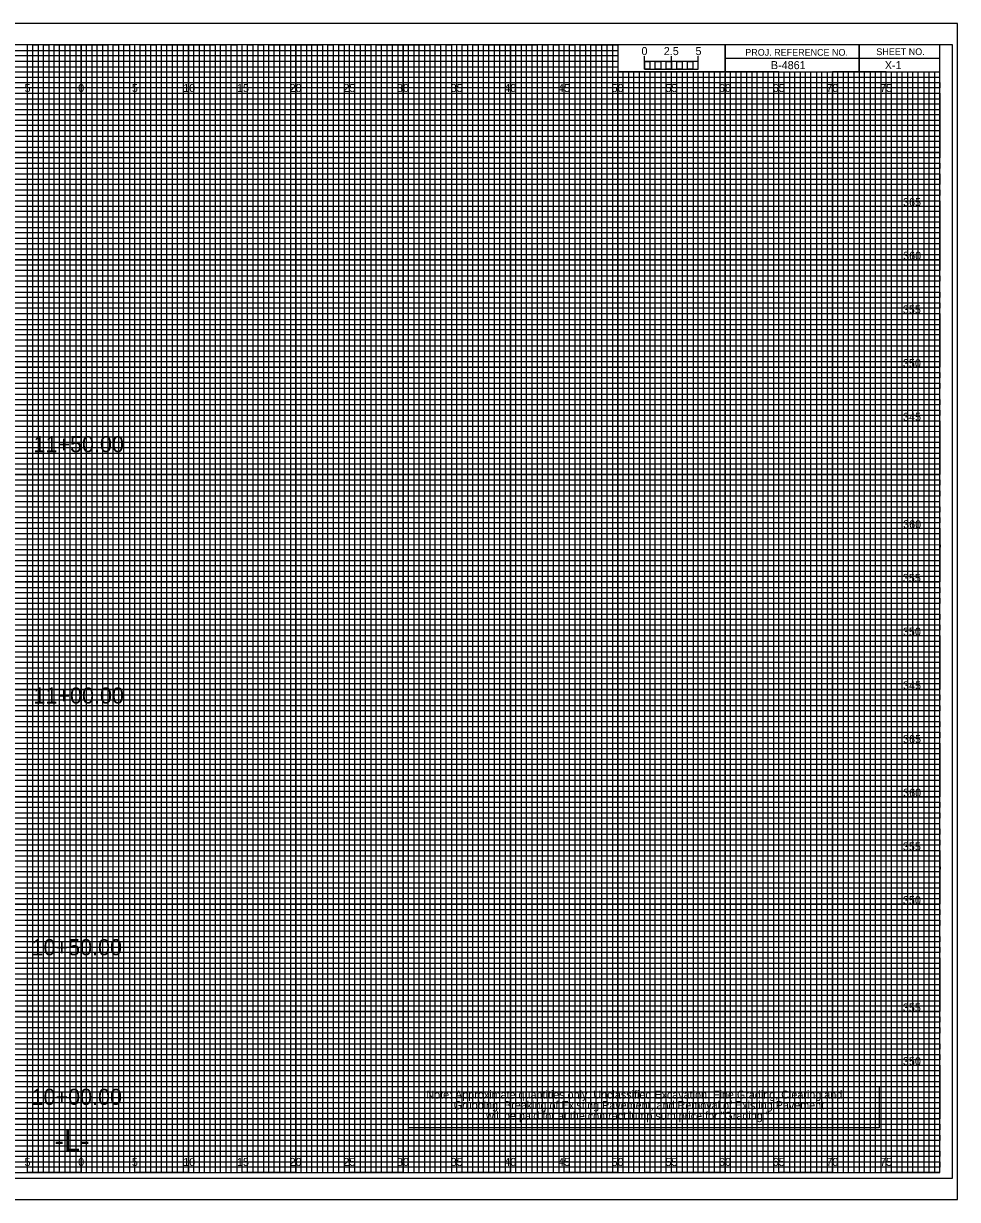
# Model space of a CAD drawing. Extents: x -7 to 266, y -5 to 437.
# Drawn here: x 74.6 to 161.7, y -2.5 to 107 of the extents above; entities that cross this region are included whole.
import ezdxf

# ---------------------------------------------------------------- set-up
doc = ezdxf.new("R2010")
doc.units = 0
for name, color, linetype in [('Exist XS Center Line Elevation Label', 7, 'Continuous'), ('Exist XS Ground Line', 7, 'Continuous'), ('Prop XS Dump Level', 7, 'Continuous'), ('Prop XS EOT Tick Mark', 7, 'Continuous'), ('Prop XS Finish Grade', 7, 'Continuous'), ('Prop XS Finish Grade Concrete', 7, 'Continuous'), ('Prop XS Finish Grade CurbGutter', 7, 'Continuous'), ('Prop XS Finish Grade Earthwork', 7, 'Continuous'), ('Prop XS Finish Grade Pavement', 7, 'Continuous'), ('Prop XS Geopak Shape', 7, 'Continuous'), ('Prop XS Hydro Elevations', 7, 'Continuous'), ('Prop XS Pvmt Edge Slope', 7, 'Continuous'), ('Prop XS SE Text', 7, 'Continuous'), ('Prop XS Side Slope Text', 7, 'Continuous'), ('Prop XS SS Elevation Text', 7, 'Continuous'), ('Prop XS Subgrade CurbGutter', 7, 'Continuous'), ('Prop XS Subgrade Earthwork', 7, 'Continuous'), ('Prop XSC Text', 7, 'Continuous'), ('Typical Guardrail CELL', 7, 'Continuous')]:
    doc.layers.add(name, color=color, linetype=linetype)

msp = doc.modelspace()

# ---------------------------------------------------------------- linework, layer by layer
at = {"layer": 'Exist XS Center Line Elevation Label'}
for points in [[(72.5, 0), (77.5, 0), (77.5, 105), (82.5, 105), (82.5, 0), (87.5, 0), (87.5, 105), (92.5, 105), (92.5, 0), (97.5, 0), (97.5, 105), (102.5, 105), (102.5, 0), (107.5, 0), (107.5, 105), (112.5, 105), (112.5, 0), (117.5, 0), (117.5, 105), (122.5, 105), (122.5, 0), (127.5, 0), (127.5, 105), (129.97, 105), (130, 105), (130, 102.5), (132.5, 102.5), (132.5, 0), (137.5, 0), (137.5, 102.5), (142.5, 102.5), (142.5, 0), (147.5, 0), (147.5, 102.5), (152.5, 102.5), (152.5, 0), (157.5, 0), (157.5, 102.5)], [(0, 102.5), (137.5, 102.5)], [(0, 92.5), (160, 92.5), (160, 97.5), (0, 97.5)], [(0, 82.5), (160, 82.5), (160, 87.5), (0, 87.5)], [(0, 72.5), (160, 72.5), (160, 77.5), (0, 77.5)], [(0, 62.5), (160, 62.5), (160, 67.5), (0, 67.5)], [(0, 52.5), (160, 52.5), (160, 57.5), (0, 57.5)], [(0, 42.5), (160, 42.5), (160, 47.5), (0, 47.5)], [(0, 32.5), (160, 32.5), (160, 37.5), (0, 37.5)], [(0, 22.5), (160, 22.5), (160, 27.5), (0, 27.5)], [(0, 12.5), (160, 12.5), (160, 17.5), (0, 17.5)], [(0, 2.5), (160, 2.5), (160, 7.5), (0, 7.5)]]:
    msp.add_lwpolyline(points, dxfattribs=at)
at = {"layer": 'Exist XS Ground Line'}
for p, q in [((75, 105), (70, 105)), ((75, 0), (75, 105)), ((85, 105), (80, 105)), ((80, 105), (80, 0)), ((85, 0), (85, 105)), ((95, 105), (90, 105)), ((90, 105), (90, 0)), ((95, 0), (95, 105)), ((105, 105), (100, 105)), ((100, 105), (100, 0)), ((105, 0), (105, 105)), ((115, 105), (110, 105)), ((110, 105), (110, 0)), ((115, 0), (115, 105)), ((125, 105), (120, 105)), ((120, 105), (120, 0)), ((125, 0), (125, 105)), ((130, 105), (130, 0)), ((135, 0), (135, 102.5)), ((145, 102.5), (140, 102.5)), ((140, 102.5), (140, 0)), ((145, 0), (145, 102.5)), ((155, 102.5), (150, 102.5)), ((150, 102.5), (150, 0)), ((155, 0), (155, 102.5)), ((80, 0), (75, 0)), ((90, 0), (85, 0)), ((100, 0), (95, 0)), ((110, 0), (105, 0)), ((120, 0), (115, 0)), ((130, 0), (125, 0)), ((140, 0), (135, 0)), ((150, 0), (145, 0)), ((160, 0), (155, 0)), ((160, 0), (160, 0))]:
    msp.add_line(p, q, dxfattribs=at)
for points in [[(0, 100), (160, 100), (160, 95), (0, 95)], [(0, 90), (160, 90), (160, 85), (0, 85)], [(0, 80), (160, 80), (160, 75), (0, 75)], [(0, 70), (160, 70), (160, 65), (0, 65)], [(0, 60), (160, 60), (160, 55), (0, 55)], [(0, 50), (160, 50), (160, 45), (0, 45)], [(0, 40), (160, 40), (160, 35), (0, 35)], [(0, 30), (160, 30), (160, 25), (0, 25)], [(0, 20), (160, 20), (160, 15), (0, 15)], [(0, 10), (160, 10), (160, 5), (0, 5)]]:
    msp.add_lwpolyline(points, dxfattribs=at)
at = {"layer": 'Prop XS Finish Grade'}
for p, q in [((75, 0), (75, 105)), ((80, 0), (80, 105)), ((85, 0), (85, 105)), ((90, 0), (90, 105)), ((95, 0), (95, 105)), ((100, 0), (100, 105)), ((105, 0), (105, 105)), ((110, 0), (110, 105)), ((115, 0), (115, 105)), ((120, 0), (120, 105)), ((125, 0), (125, 105)), ((130, 0), (130, 102.34)), ((135, 0), (135, 102.34)), ((140, 0), (140, 102.34)), ((145, 0), (145, 102.34)), ((150, 0), (150, 102.34)), ((155, 0), (155, 102.34)), ((0, 100), (160, 100)), ((0, 95), (160, 95)), ((0, 90), (160, 90)), ((0, 85), (160, 85)), ((0, 80), (160, 80)), ((0, 75), (160, 75)), ((0, 70), (160, 70)), ((0, 65), (160, 65)), ((0, 60), (160, 60)), ((0, 55), (160, 55)), ((0, 50), (160, 50)), ((0, 45), (160, 45)), ((0, 40), (160, 40)), ((0, 35), (160, 35)), ((0, 30), (160, 30)), ((0, 25), (160, 25)), ((0, 20), (160, 20)), ((0, 15), (160, 15)), ((0, 10), (160, 10)), ((0, 5), (160, 5))]:
    msp.add_line(p, q, dxfattribs=at)
at = {"layer": 'Prop XS Finish Grade Earthwork'}
msp.add_lwpolyline([(-6.7, -2.5), (161.65, -2.5), (161.65, 107), (-6.7, 107)], close=True, dxfattribs=at)
at = {"layer": 'Prop XS Hydro Elevations'}
for p, q in [((152.5, 105), (152.5, 102.5)), ((152.5, 102.5), (152.5, 105)), ((160, 103.75), (140, 103.75)), ((140, 103.75), (140, 102.5)), ((140, 102.5), (160, 102.5))]:
    msp.add_line(p, q, dxfattribs=at)
for points in [[(160, 105), (0, 105), (0, 0), (160, 0)], [(140, 105), (130, 105), (130, 102.52), (140, 102.52)], [(160, 105), (140, 105), (140, 102.5), (160, 102.5)]]:
    msp.add_lwpolyline(points, close=True, dxfattribs=at)
at = {"layer": 'Prop XS Pvmt Edge Slope'}
msp.add_lwpolyline([(-5.4, -0.5), (161.2, -0.5), (161.2, 105), (-5.4, 105)], close=True, dxfattribs=at)
at = {"layer": 'Prop XS SE Text'}
for p, q in [((0, 104.5), (130, 104.5)), ((130, 104.5), (130, 103.99)), ((130, 103.99), (0, 103.99)), ((0, 103.5), (130, 103.5)), ((130, 102.95), (0, 102.95)), ((130, 103.5), (130, 102.95)), ((0, 102), (160, 102))]:
    msp.add_line(p, q, dxfattribs=at)
for points in [[(0, 101.5), (135, 101.5), (160, 101.5), (160, 101), (0, 101)], [(0, 100.5), (160, 100.5), (160, 99.5), (0, 99.5)], [(0, 99), (160, 99), (160, 98.5), (0, 98.49)], [(0, 98), (160, 98), (160, 97), (0, 97)], [(0, 96.5), (160, 96.5), (160, 96), (0, 96)], [(0, 95.5), (160, 95.5), (160, 94.5), (0, 94.5)], [(0, 94), (160, 94), (160, 93.5), (0, 93.5)], [(0, 93), (160, 93), (160, 92), (0, 92)], [(0, 91.5), (160, 91.5), (160, 91), (0, 91)], [(0, 90.5), (160, 90.5), (160, 89.5), (0, 89.5)], [(0, 89), (160, 89), (160, 88.5), (0, 88.5)], [(0, 88), (160, 88), (160, 86.98), (160, 86.5), (160, 86), (0, 86)], [(0, 87), (160, 87), (160, 86.5), (0, 86.5)], [(0, 85.5), (160, 85.5), (160, 84.5), (0, 84.52)], [(0, 84.52), (160, 84.5), (160, 84), (0, 84)], [(0, 83.5), (160, 83.5), (160, 83), (0, 83)], [(0, 82), (160, 82), (160, 81.5), (0, 81.5)], [(0, 81), (160, 81), (160, 80.5), (0, 80.5)], [(-0.04, 79.45), (160, 79.45), (160, 78.94), (-0.04, 78.94)], [(0, 78.5), (160, 78.5), (160, 78), (0, 78)], [(0, 77), (160, 77), (160, 76.5), (0, 76.5)], [(0, 76), (160, 76), (160, 75.5), (0, 75.5)], [(0, 74.5), (160, 74.5), (160, 74), (0, 74)], [(0, 73.5), (160, 73.5), (160, 73), (0, 73)], [(0, 72), (160, 72), (160, 71.5), (0, 71.5)], [(0, 71), (160, 71), (160, 70.5), (0, 70.5)], [(0, 69.5), (160, 69.5), (160, 68.99), (0, 69)], [(0, 68.5), (160, 68.5), (160, 68), (0, 68)], [(0, 67), (160, 67), (160, 66.5), (0, 66.5)], [(0, 66), (160, 66), (160, 65.5), (0, 65.5)], [(0, 64.5), (160, 64.5), (160, 64), (0, 64)], [(0, 63.5), (160, 63.5), (160, 63), (0, 63)], [(0, 62), (160, 62), (160, 61.5), (0, 61.5)], [(0, 61), (160, 61), (160, 60.5), (0, 60.5)], [(0, 59.5), (160, 59.5), (160, 59), (0, 59)], [(0, 58.5), (160.03, 58.45), (160, 58), (0, 58)], [(0, 57), (160, 57), (160, 56.5), (0, 56.5)], [(0, 56), (160, 56), (160, 55.5), (0, 55.5)], [(0, 54.5), (160, 54.5), (160, 54), (0, 54)], [(0, 53.5), (160, 53.5), (160, 53), (0, 53)], [(0, 52), (160, 52), (160, 51.5), (0, 51.5)], [(0, 51), (160, 51), (160, 50.5), (0, 50.5)], [(0, 49.5), (160, 49.5), (160, 49), (0, 49)], [(0, 48.5), (160, 48.5), (160, 48), (0, 48)], [(0, 47), (160, 47), (160, 46.5), (0, 46.5)], [(0, 46), (160, 46), (160, 45.5), (0, 45.5)], [(0, 44.5), (160, 44.5), (160, 44), (0, 44)], [(0, 43.5), (160, 43.5), (160, 43), (0, 43)], [(0, 42), (160, 42), (160, 41.5), (0, 41.5)], [(0, 41), (160, 41), (160, 40.5), (0, 40.5)], [(0, 39.5), (160, 39.5), (160, 38.99), (0, 39)], [(0, 38.5), (160, 38.5), (160, 38), (0, 38)], [(0, 37), (160, 37), (160, 36.5), (0, 36.5)], [(0, 36), (160, 36), (160, 35.5), (0, 35.5)], [(0, 34.5), (160, 34.5), (160, 34), (0, 34)], [(0, 33.5), (160, 33.5), (160, 33), (0, 33)], [(0, 32), (160, 32), (160, 31.5), (0, 31.5)], [(0, 31), (160, 31), (160, 30.5), (0, 30.5)], [(0, 29.5), (160, 29.5), (160, 29), (0, 29)], [(0, 28.5), (160.03, 28.46), (160, 28), (0, 28)], [(0, 27), (160, 27), (160, 26.5), (0, 26.5)], [(0, 26), (160, 26), (160, 25.5), (0, 25.5)], [(0, 24.5), (160, 24.5), (160, 24), (0, 24)], [(0, 23.5), (160, 23.5), (160, 23), (0, 23)], [(0, 22), (160, 22), (160, 21.5), (0, 21.5)], [(0, 21), (160, 21), (160, 20.5), (0, 20.5)], [(0, 19.5), (160, 19.5), (160, 19), (0, 19)], [(0, 18.5), (160, 18.5), (160, 18), (0, 18)], [(0, 17), (160, 17), (160, 16.5), (0, 16.5)], [(0, 16), (160, 16), (160, 15.5), (0, 15.5)], [(0, 14.5), (160, 14.5), (160, 14), (0, 14)], [(0, 13.5), (160, 13.5), (160, 13), (0, 13)], [(0, 12), (160, 12), (160, 11.5), (0, 11.5)], [(0, 11), (160, 11), (160, 10.5), (0, 10.5)], [(0, 9.5), (160, 9.5), (160, 9), (0, 9)], [(0, 8.5), (160, 8.5), (160, 8), (0, 8)], [(0, 7), (160, 7), (160, 6.5), (0, 6.5)], [(0, 6), (160, 6), (160, 5.5), (0, 5.5)], [(0, 4.5), (160, 4.5), (160, 4), (0, 4)], [(0, 3.5), (160, 3.5), (160, 3), (0, 3)], [(0, 2), (160, 2), (160, 1.5), (0, 1.5)], [(0, 1), (160, 1), (160, 0.5), (0, 0.5)]]:
    msp.add_lwpolyline(points, dxfattribs=at)
at = {"layer": 'Prop XS Side Slope Text'}
for p, q in [((132.5, 102.75), (132.5, 103.95)), ((132.5, 103.45), (132.5, 103.95)), ((135, 102.75), (135, 103.95)), ((137.5, 102.75), (137.5, 103.95)), ((137.5, 103.45), (137.5, 103.95))]:
    msp.add_line(p, q, dxfattribs=at)
for points in [[(137.5, 103.45), (132.5, 103.45), (132.5, 102.75), (137.5, 102.75)], [(132.5, 103.45), (133, 103.45), (133, 102.75), (132.5, 102.75)], [(133.5, 103.45), (134, 103.45), (134, 102.75), (133.5, 102.75)], [(134.5, 103.45), (135, 103.45), (135, 102.75), (134.5, 102.75)], [(135.5, 103.45), (136, 103.45), (136, 102.75), (135.5, 102.75)], [(136.5, 103.45), (137, 103.45), (137, 102.75), (136.5, 102.75)]]:
    msp.add_lwpolyline(points, close=True, dxfattribs=at)
at = {"layer": 'Prop XS SS Elevation Text'}
for p, q in [((133.5, 102.5), (133, 102.5)), ((133, 102.5), (133, 0)), ((133.5, 0), (133.5, 102.5)), ((134.5, 102.5), (134, 102.5)), ((134, 102.5), (134, 0)), ((134.5, 0), (134.5, 102.5)), ((133, 0), (132.5, 0)), ((134, 0), (133.5, 0))]:
    msp.add_line(p, q, dxfattribs=at)
for points in [[(75, 0), (75.5, 0), (75.5, 105), (76, 105), (76, 0)], [(76, 0), (76.5, 0), (76.5, 105), (77, 105), (77, 0)], [(77.5, 0), (78, 0), (78, 105), (78.5, 105), (78.5, 0)], [(78.5, 0), (79, 0), (79, 105), (79.5, 105), (79.5, 0)], [(80, 0), (80.5, 0), (80.5, 105), (81, 105), (81, 0)], [(81, 0), (81.5, 0), (81.5, 105), (82, 105), (82, 0)], [(82.5, 0), (83, 0), (83, 105), (83.5, 105), (83.5, 0)], [(83.5, 0), (84, 0), (84, 105), (84.5, 105), (84.5, 0)], [(85, 0), (85.5, 0), (85.5, 105), (86, 105), (86, 0)], [(86, 0), (86.5, 0), (86.5, 105), (87, 105), (87, 0)], [(87.5, 0), (88, 0), (88, 105), (88.5, 105), (88.5, 0)], [(88.5, 0), (89, 0), (89, 105), (89.5, 105), (89.5, 0)], [(90, 0), (90.5, 0), (90.5, 105), (91, 105), (91, 0)], [(91, 0), (91.5, 0), (91.5, 105), (92, 105), (92, 0)], [(92.5, 0), (93, 0), (93, 105), (93.5, 105), (93.5, 0)], [(93.5, 0), (94, 0), (94, 105), (94.5, 105), (94.5, 0)], [(95, 0), (95.5, 0), (95.5, 105), (96, 105), (96, 0)], [(96, 0), (96.5, 0), (96.5, 105), (97, 105), (97, 0)], [(97.5, 0), (98, 0), (98, 105), (98.5, 105), (98.5, 0)], [(98.5, 0), (99, 0), (99, 105), (99.5, 105), (99.5, 0)], [(100, 0), (100.5, 0), (100.5, 105), (101, 105), (101, 0)], [(101, 0), (101.5, 0), (101.5, 105), (102, 105), (102, 0)], [(102.5, 0), (103, 0), (103, 105), (103.5, 105), (103.5, 0)], [(103.5, 0), (104, 0), (104, 105), (104.5, 105), (104.5, 0)], [(105, 0), (105.5, 0), (105.5, 105), (106, 105), (106, 0)], [(106, 0), (106.5, 0), (106.5, 105), (107, 105), (107, 0)], [(107.5, 0), (108, 0), (108, 105), (108.5, 105), (108.5, 0)], [(108.5, 0), (109, 0), (109, 105), (109.5, 105), (109.5, 0)], [(110, 0), (110.5, 0), (110.5, 105), (111, 105), (111, 0)], [(111, 0), (111.5, 0), (111.5, 105), (112, 105), (112, 0)], [(112.5, 0), (113, 0), (113, 105), (113.5, 105), (113.5, 0)], [(113.5, 0), (114, 0), (114, 105), (114.5, 105), (114.5, 0)], [(115, 0), (115.5, 0), (115.5, 105), (116, 105), (116, 0)], [(116, 0), (116.5, 0), (116.5, 105), (117, 105), (117, 0)], [(117.5, 0), (118, 0), (118, 105), (118.5, 105), (118.5, 0)], [(118.5, 0), (119, 0), (119, 105), (119.5, 105), (119.5, 0)], [(120, 0), (120.5, 0), (120.5, 105), (121, 105), (121, 0)], [(121, 0), (121.5, 0), (121.5, 105), (122, 105), (122, 0)], [(122.5, 0), (123, 0), (123, 105), (123.5, 105), (123.5, 0)], [(123.5, 0), (124, 0), (124, 105), (124.5, 105), (124.5, 0)], [(125, 0), (125.5, 0), (125.5, 105), (126, 105), (126, 0)], [(126, 0), (126.5, 0), (126.5, 105), (127, 105), (127, 0)], [(127.5, 0), (128, 0), (128, 105), (128.5, 105), (128.5, 0)], [(128.5, 0), (129, 0), (129, 105), (129.5, 105), (129.5, 0)], [(130, 0), (130.5, 0), (130.5, 102.5), (131.01, 102.5), (131.01, 0)], [(131, 0), (131.5, 0), (131.5, 102.5), (132, 102.5), (132, 0)], [(135, 0), (135.49, 0), (135.49, 102.5), (136, 102.5), (136, 0)], [(136, 0), (136.5, 0), (136.5, 102.5), (137.03, 102.5), (137.03, 0)], [(137.5, 0), (138, 0), (138, 102.5), (138.5, 102.5), (138.5, 0)], [(138.5, 0), (139, 0), (139, 102.5), (139.5, 102.5), (139.5, 0)], [(140, 0), (140.5, 0), (140.5, 102.5), (141, 102.5), (141, 0)], [(141, 0), (141.5, 0), (141.5, 102.5), (142, 102.5), (142, 0)], [(142.5, 0), (143, 0), (143, 102.5), (143.5, 102.5), (143.5, 0)], [(143.5, 0), (144, 0), (144, 102.5), (144.5, 102.5), (144.5, 0)], [(145, 0), (145.5, 0), (145.5, 102.5), (146, 102.5), (146, 0)], [(146, 0), (146.5, 0), (146.5, 102.5), (147, 102.5), (147, 0)], [(147.5, 0), (148, 0), (148, 102.5), (148.5, 102.5), (148.5, 0)], [(148.5, 0), (149, 0), (149, 102.5), (149.5, 102.5), (149.5, 0)], [(150, 0), (150.5, 0), (150.5, 102.5), (151, 102.5), (151, 0)], [(151, 0), (151.5, 0), (151.5, 102.5), (152, 102.5), (152, 0)], [(152.5, 0), (153, 0), (153, 102.5), (153.5, 102.5), (153.5, 0)], [(153.5, 0), (154, 0), (154, 102.5), (154.5, 102.5), (154.5, 0)], [(155, 0), (155.5, 0), (155.5, 102.5), (156, 102.5), (156, 0)], [(156, 0), (156.5, 0), (156.5, 102.5), (157, 102.5), (157, 0)], [(157.5, 0), (158, 0), (158, 102.5), (158.5, 102.5), (158.5, 0)], [(158.5, 0), (159, 0), (159, 102.5), (159.5, 102.5), (159.5, 0)]]:
    msp.add_lwpolyline(points, dxfattribs=at)
at = {"layer": 'Prop XS Subgrade CurbGutter'}
msp.add_lwpolyline([(110.51, 8.01), (154.35, 8.01), (154.35, 4.17), (110.51, 4.17)], close=True, dxfattribs=at)
at = {"layer": 'Prop XS Subgrade Earthwork'}
for p, q in [((161.65, 107), (-6.7, 107)), ((-6.7, -2.5), (161.65, -2.5))]:
    msp.add_line(p, q, dxfattribs=at)

# ---------------------------------------------------------------- texts
at = {"layer": 'Prop XS Dump Level'}
msp.add_text('-L-', height=2, dxfattribs=at).set_placement((77.53, 2))
at = {"layer": 'Prop XS EOT Tick Mark'}
msp.add_text('X-1', height=0.75, dxfattribs=at).set_placement((154.88, 102.75))
at = {"layer": 'Prop XS Finish Grade Concrete'}
for s, p in [('365', (156.58, 90)), ('360', (156.59, 85)), ('355', (156.56, 80)), ('350', (156.57, 75)), ('345', (156.58, 70)), ('360', (156.59, 60)), ('355', (156.56, 55)), ('350', (156.57, 50)), ('345', (156.58, 45)), ('365', (156.58, 40)), ('360', (156.59, 35)), ('355', (156.56, 30)), ('350', (156.57, 25)), ('355', (156.56, 15)), ('350', (156.57, 10))]:
    msp.add_text(s, height=0.75, dxfattribs=at).set_placement(p)
at = {"layer": 'Prop XS Finish Grade CurbGutter'}
for s, p in [('Note: Approximate quantities only. Unclassified Excavation, Fine Grading, Clearing and', (112.17, 6.89)), ('Grubbing, Breaking of Existing Pavement, and Removal of Existing Pavement', (114.72, 5.91)), ('will be paid for at the contract lump sum price for "Grading."', (117.73, 4.92))]:
    msp.add_text(s, height=0.75, dxfattribs=at).set_placement(p)
at = {"layer": 'Prop XS Finish Grade Pavement'}
msp.add_text('B-4861', height=0.75, dxfattribs=at).set_placement((144.27, 102.75))
at = {"layer": 'Prop XS Geopak Shape'}
for s, p in [('2.5', (134.29, 104.06)), ('5', (137.24, 104.06))]:
    msp.add_text(s, height=0.75, dxfattribs=at).set_placement(p)
at = {"layer": 'Prop XS Hydro Elevations'}
for s, p in [('PROJ. REFERENCE NO.', (141.88, 104)), ('SHEET NO.', (154.09, 104.06))]:
    msp.add_text(s, height=0.625, dxfattribs=at).set_placement(p)
at = {"layer": 'Prop XS Side Slope Text'}
msp.add_text('0', height=0.75, dxfattribs=at).set_placement((132.21, 104.06))
at = {"layer": 'Prop XSC Text'}
for s, p in [('11+50.00', (75.57, 67.08)), ('11+00.00', (75.57, 43.68)), ('10+50.00', (75.39, 20.24)), ('10+00.00', (75.39, 6.31))]:
    msp.add_text(s, height=1.5, dxfattribs=at).set_placement(p)
at = {"layer": 'Typical Guardrail CELL'}
for s, p in [('5', (74.74, 100.62)), ('0', (79.73, 100.62)), ('0', (79.73, 100.62)), ('5', (84.74, 100.62)), ('10', (89.52, 100.62)), ('15', (94.53, 100.62)), ('20', (99.43, 100.62)), ('25', (104.44, 100.62)), ('30', (109.43, 100.62)), ('35', (114.44, 100.62)), ('40', (119.43, 100.62)), ('45', (124.44, 100.62)), ('50', (129.43, 100.62)), ('55', (134.44, 100.62)), ('60', (139.43, 100.62)), ('65', (144.44, 100.62)), ('70', (149.43, 100.62)), ('75', (154.44, 100.62)), ('5', (74.74, 0.62)), ('0', (79.73, 0.62)), ('0', (79.73, 0.62)), ('5', (84.74, 0.62)), ('10', (89.52, 0.62)), ('15', (94.53, 0.62)), ('20', (99.43, 0.62)), ('25', (104.44, 0.62)), ('30', (109.43, 0.62)), ('35', (114.44, 0.62)), ('40', (119.43, 0.62)), ('45', (124.44, 0.62)), ('50', (129.43, 0.62)), ('55', (134.44, 0.62)), ('60', (139.43, 0.62)), ('65', (144.44, 0.62)), ('70', (149.43, 0.62)), ('75', (154.44, 0.62))]:
    msp.add_text(s, height=0.75, dxfattribs=at).set_placement(p)

doc.saveas('drawing.dxf')
